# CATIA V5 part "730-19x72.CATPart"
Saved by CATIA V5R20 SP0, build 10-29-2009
Part number: 730-19x72
Definition: NONE
Nomenclature: 730-19x72
Source: Unknown
Description: 730-19x72
Bounding box of the stored display mesh (mm): x -12.441 to 12.441, y -11.818 to 11.818, z 0 to 72
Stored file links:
  C:\Users\Utente\Desktop\IO LAVORO\3D X SITO CF\X SITO\730\730-19x72.CATPart
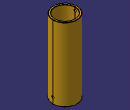
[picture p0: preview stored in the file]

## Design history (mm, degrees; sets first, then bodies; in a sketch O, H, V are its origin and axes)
Body1 "730-19x72" (main body)
  Solid1: solid without history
